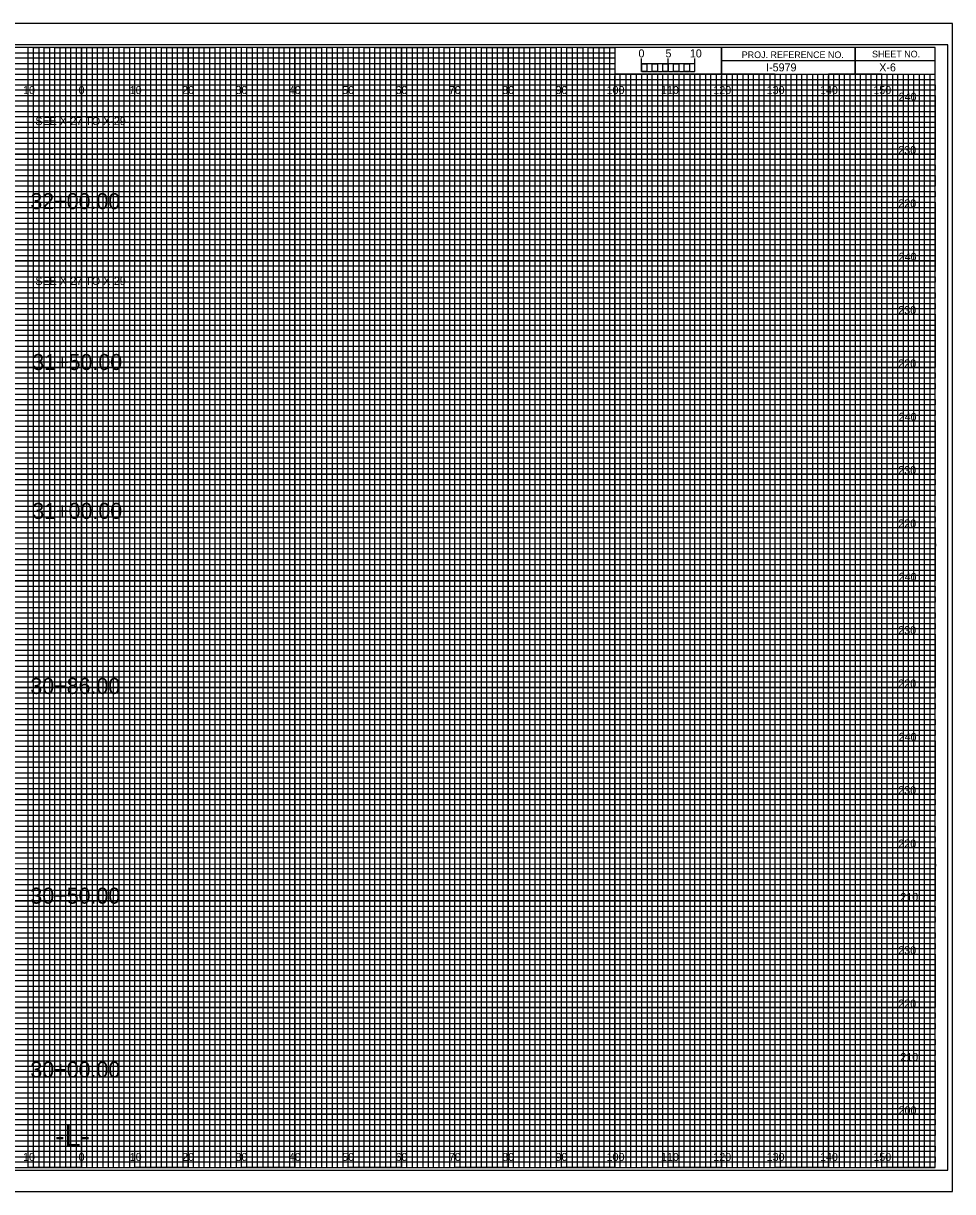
# Model space of a CAD drawing. Extents: x -13 to 359, y -5 to 2854.
# Drawn here: x 149.1 to 323.3, y 1095.5 to 1314.5 of the extents above; entities that cross this region are included whole.
import ezdxf

# ---------------------------------------------------------------- set-up
doc = ezdxf.new("R2010")
doc.units = 0
for name, color, linetype in [('Exist CMT Pavement', 7, 'Continuous'), ('Exist Cross Section Cell', 7, 'Continuous'), ('Exist XS Ground Line', 7, 'Continuous'), ('Prop CMT Conc Surface', 7, 'Continuous'), ('Prop CMT Concrete Structures', 7, 'Continuous'), ('Prop CMT DNC', 7, 'Continuous'), ('Prop CMT Pvmt Course 1', 7, 'Continuous'), ('Prop CMT Pvmt Course 1 CG', 7, 'Continuous'), ('Prop CMT Pvmt Course 1 Wedge', 7, 'Continuous'), ('Prop CMT Pvmt Course 2', 7, 'Continuous'), ('Prop CMT Pvmt Course 2 Wedge', 7, 'Continuous'), ('Prop CMT Pvmt Course 3', 7, 'Continuous'), ('Prop CMT Pvmt Course 3 Wedge', 7, 'Continuous'), ('Prop CMT Pvmt Wedge Surface 3', 7, 'Continuous'), ('Prop CMT Shear Line', 7, 'Continuous'), ('Prop CMT Slope Grass', 7, 'Continuous'), ('Prop CMT Subgrade Earthwork', 7, 'Continuous'), ('Scratch_Level_0', 7, 'Continuous')]:
    doc.layers.add(name, color=color, linetype=linetype)

msp = doc.modelspace()

# ---------------------------------------------------------------- linework, layer by layer
at = {"layer": 'Exist XS Ground Line'}
for p, q in [((150, 1310), (140, 1310)), ((150, 1100), (150, 1310)), ((170, 1310), (160, 1310)), ((160, 1310), (160, 1100)), ((170, 1100), (170, 1310)), ((190, 1310), (180, 1310)), ((180, 1310), (180, 1100)), ((190, 1100), (190, 1310)), ((210, 1310), (200, 1310)), ((200, 1310), (200, 1100)), ((210, 1100), (210, 1310)), ((230, 1310), (220, 1310)), ((220, 1310), (220, 1100)), ((230, 1100), (230, 1310)), ((250, 1310), (240, 1310)), ((240, 1310), (240, 1100)), ((250, 1100), (250, 1310)), ((260, 1310), (260, 1100)), ((270, 1100), (270, 1305)), ((290, 1305), (280, 1305)), ((280, 1305), (280, 1100)), ((290, 1100), (290, 1305)), ((310, 1305), (300, 1305)), ((300, 1305), (300, 1100)), ((310, 1100), (310, 1305)), ((160, 1100), (150, 1100)), ((180, 1100), (170, 1100)), ((200, 1100), (190, 1100)), ((220, 1100), (210, 1100)), ((240, 1100), (230, 1100)), ((260, 1100), (250, 1100)), ((280, 1100), (270, 1100)), ((300, 1100), (290, 1100)), ((320, 1100), (310, 1100)), ((320, 1100), (320, 1100))]:
    msp.add_line(p, q, dxfattribs=at)
for points in [[(0, 1300), (320, 1300), (320, 1290), (0, 1290)], [(0, 1280), (320, 1280), (320, 1270), (0, 1270)], [(0, 1260), (320, 1260), (320, 1250), (0, 1250)], [(0, 1240), (320, 1240), (320, 1230), (0, 1230)], [(0, 1220), (320, 1220), (320, 1210), (0, 1210)], [(0, 1200), (320, 1200), (320, 1190), (0, 1190)], [(0, 1180), (320, 1180), (320, 1170), (0, 1170)], [(0, 1160), (320, 1160), (320, 1150), (0, 1150)], [(0, 1140), (320, 1140), (320, 1130), (0, 1130)], [(0, 1120), (320, 1120), (320, 1110), (0, 1110)]]:
    msp.add_lwpolyline(points, dxfattribs=at)
at = {"layer": 'Prop CMT Conc Surface'}
for p, q in [((265, 1305.49), (265, 1307.9)), ((265, 1306.9), (265, 1307.9)), ((270, 1305.49), (270, 1307.9)), ((275, 1305.49), (275, 1307.9)), ((275, 1306.9), (275, 1307.9))]:
    msp.add_line(p, q, dxfattribs=at)
for points in [[(275, 1306.9), (265, 1306.9), (265, 1305.49), (275, 1305.49)], [(265, 1306.9), (266, 1306.9), (266, 1305.49), (265, 1305.49)], [(267, 1306.9), (268, 1306.9), (268, 1305.49), (267, 1305.49)], [(269, 1306.9), (270, 1306.9), (270, 1305.49), (269, 1305.49)], [(271, 1306.9), (272, 1306.9), (272, 1305.49), (271, 1305.49)], [(273, 1306.9), (274, 1306.9), (274, 1305.49), (273, 1305.49)]]:
    msp.add_lwpolyline(points, close=True, dxfattribs=at)
at = {"layer": 'Prop CMT Concrete Structures'}
for p, q in [((305, 1310), (305, 1305)), ((305, 1305), (305, 1310)), ((280, 1307.5), (280, 1305)), ((320, 1307.49), (280, 1307.49)), ((280, 1305), (320, 1305))]:
    msp.add_line(p, q, dxfattribs=at)
for points in [[(320, 1310), (0, 1310), (0, 1100), (320, 1100)], [(280, 1310), (260, 1310), (260, 1305.03), (280, 1305.03)], [(320, 1310), (280, 1310), (280, 1305), (320, 1305)]]:
    msp.add_lwpolyline(points, close=True, dxfattribs=at)
at = {"layer": 'Prop CMT DNC'}
for p, q in [((323.3, 1314.5), (-13.4, 1314.5)), ((-13.4, 1095.5), (323.3, 1095.5))]:
    msp.add_line(p, q, dxfattribs=at)
at = {"layer": 'Prop CMT Pvmt Course 1'}
for p, q in [((0, 1309), (260, 1309)), ((260, 1307.98), (0, 1307.98)), ((260, 1309), (260, 1307.98)), ((0, 1307), (260, 1307)), ((260, 1305.89), (0, 1305.89)), ((260, 1307), (260, 1305.89)), ((0, 1304), (320, 1304))]:
    msp.add_line(p, q, dxfattribs=at)
for points in [[(0, 1303), (270, 1303), (320, 1303), (320, 1302), (0, 1302)], [(0, 1301), (320, 1301), (320, 1299), (0, 1299)], [(0, 1298), (320, 1298), (320, 1297), (0, 1296.98)], [(0, 1296), (320, 1296), (320, 1294), (0, 1294)], [(0, 1293), (320, 1293), (320, 1292), (0, 1292)], [(0, 1291), (320, 1291), (320, 1289), (0, 1289)], [(0, 1288), (320, 1288), (320, 1287), (0, 1287)], [(0, 1286), (320, 1286), (320, 1284), (0, 1284)], [(0, 1283), (320, 1283), (320, 1282), (0, 1282)], [(0, 1281), (320, 1281), (320, 1279), (0, 1279)], [(0, 1278), (320, 1278), (320, 1277), (0, 1277)], [(0, 1276), (320, 1276), (320, 1273.95), (320, 1273), (320, 1272), (0, 1272)], [(0, 1274), (320, 1274), (320, 1273), (0, 1273)], [(0, 1271), (320, 1271), (320, 1269), (0, 1269.03)], [(0, 1269.03), (320, 1269), (320, 1268), (0, 1268)], [(0, 1267), (320, 1267), (320, 1266), (0, 1266)], [(0, 1264), (320, 1264), (320, 1263), (0, 1263)], [(0, 1262), (320, 1262), (320, 1261), (0, 1261)], [(-0.07, 1258.89), (320, 1258.89), (320, 1257.88), (-0.07, 1257.88)], [(0, 1257), (320, 1257), (320, 1256), (0, 1256)], [(0, 1254), (320, 1254), (320, 1253), (0, 1253)], [(0, 1252), (320, 1252), (320, 1251), (0, 1251)], [(0, 1249), (320, 1249), (320, 1248), (0, 1248)], [(0, 1247), (320, 1247), (320, 1246), (0, 1246)], [(0, 1244), (320, 1244), (320, 1243), (0, 1243)], [(0, 1242), (320, 1242), (320, 1241), (0, 1241)], [(0, 1239), (320, 1239), (319.99, 1237.98), (0, 1238)], [(0, 1237), (320, 1237), (320, 1236), (0, 1236)], [(0, 1234), (320, 1234), (320, 1233), (0, 1233)], [(0, 1232), (320, 1232), (320, 1231), (0, 1231)], [(0, 1229), (320, 1229), (320, 1228), (0, 1228)], [(0, 1227), (320, 1227), (320, 1226), (0, 1226)], [(0, 1224), (320, 1224), (320, 1223), (0, 1223)], [(0, 1222), (320, 1222), (320, 1221), (0, 1221)], [(0, 1219), (320, 1219), (320, 1218), (0, 1218)], [(0, 1216.99), (320.07, 1216.91), (320, 1216), (0, 1216)], [(0, 1214), (320, 1214), (320, 1213), (0, 1213)], [(0, 1212), (320, 1212), (320, 1211), (0, 1211)], [(0, 1209), (320, 1209), (320, 1208), (0, 1208)], [(0, 1207), (320, 1207), (320, 1206), (0, 1206)], [(0, 1204), (320, 1204), (320, 1203), (0, 1203)], [(0, 1202), (320, 1202), (320, 1201), (0, 1201)], [(0, 1199), (320, 1199), (320, 1198), (0, 1198)], [(0, 1197), (320, 1197), (320, 1196), (0, 1196)], [(0, 1194), (320, 1194), (320, 1193), (0, 1193)], [(0, 1192), (320, 1192), (320, 1191), (0, 1191)], [(0, 1189), (320, 1189), (320, 1188), (0, 1188)], [(0, 1187), (320, 1187), (320, 1186), (0, 1186)], [(0, 1184), (320, 1184), (320, 1183), (0, 1183)], [(0, 1182), (320, 1182), (320, 1181), (0, 1181)], [(0, 1179), (320, 1179), (319.99, 1177.98), (0, 1178)], [(0, 1177), (320, 1177), (320, 1176), (0, 1176)], [(0, 1174), (320, 1174), (320, 1173), (0, 1173)], [(0, 1172), (320, 1172), (320, 1171), (0, 1171)], [(0, 1169), (320, 1169), (320, 1168), (0, 1168)], [(0, 1167), (320, 1167), (320, 1166), (0, 1166)], [(0, 1164), (320, 1164), (320, 1163), (0, 1163)], [(0, 1162), (320, 1162), (320, 1161), (0, 1161)], [(0, 1159), (320, 1159), (320, 1158), (0, 1158)], [(0, 1156.99), (320.07, 1156.91), (320, 1156), (0, 1156)], [(0, 1154), (320, 1154), (320, 1153), (0, 1153)], [(0, 1152), (320, 1152), (320, 1151), (0, 1151)], [(0, 1149), (320, 1149), (320, 1148), (0, 1148)], [(0, 1147), (320, 1147), (320, 1146), (0, 1146)], [(0, 1144), (320, 1144), (320, 1143), (0, 1143)], [(0, 1142), (320, 1142), (320, 1141), (0, 1141)], [(0, 1139), (320, 1139), (320, 1138), (0, 1138)], [(0, 1137), (320, 1137), (320, 1136), (0, 1136)], [(0, 1134), (320, 1134), (320, 1133), (0, 1133)], [(0, 1132), (320, 1132), (320, 1131), (0, 1131)], [(0, 1129), (320, 1129), (320, 1128), (0, 1128)], [(0, 1127), (320, 1127), (320, 1126), (0, 1126)], [(0, 1124), (320, 1124), (320, 1123), (0, 1123)], [(0, 1122), (320, 1122), (320, 1121), (0, 1121)], [(0, 1119), (320, 1119), (320, 1118), (0, 1118)], [(0, 1117), (320, 1117), (320, 1116), (0, 1116)], [(0, 1114), (320, 1114), (320, 1113), (0, 1113)], [(0, 1112), (320, 1112), (320, 1111), (0, 1111)], [(0, 1109), (320, 1109), (320, 1108), (0, 1108)], [(0, 1107), (320, 1107), (320, 1106), (0, 1106)], [(0, 1104), (320, 1104), (320, 1103), (0, 1103)], [(0, 1102), (320, 1102), (320, 1101), (0, 1101)]]:
    msp.add_lwpolyline(points, dxfattribs=at)
at = {"layer": 'Prop CMT Pvmt Course 1 CG'}
for p, q in [((267, 1305), (266.01, 1305)), ((266.01, 1305), (266.01, 1100)), ((267, 1100), (267, 1305)), ((269, 1305), (268, 1305)), ((268, 1305), (268, 1100)), ((269, 1100), (269, 1305)), ((266.01, 1100), (265, 1100)), ((268, 1100), (267, 1100))]:
    msp.add_line(p, q, dxfattribs=at)
for points in [[(150, 1100), (151, 1100), (151, 1310), (152, 1310), (152, 1100)], [(152, 1100), (153, 1100), (153, 1310), (154, 1310), (154, 1100)], [(155, 1100), (156, 1100), (156, 1310), (157, 1310), (157, 1100)], [(157, 1100), (158, 1100), (158, 1310), (159, 1310), (159, 1100)], [(160, 1100), (161, 1100), (161, 1310), (162, 1310), (162, 1100)], [(162, 1100), (163, 1100), (163, 1310), (164, 1310), (164, 1100)], [(165, 1100), (166, 1100), (166, 1310), (167, 1310), (167, 1100)], [(167, 1100), (168, 1100), (168, 1310), (169, 1310), (169, 1100)], [(170, 1100), (171, 1100), (171, 1310), (172, 1310), (172, 1100)], [(172, 1100), (173, 1100), (173, 1310), (174, 1310), (174, 1100)], [(175, 1100), (176, 1100), (176, 1310), (177, 1310), (177, 1100)], [(177, 1100), (178, 1100), (178, 1310), (179, 1310), (179, 1100)], [(180, 1100), (181, 1100), (181, 1310), (182, 1310), (182, 1100)], [(182, 1100), (183, 1100), (183, 1310), (184, 1310), (184, 1100)], [(185, 1100), (186, 1100), (186, 1310), (187, 1310), (187, 1100)], [(187, 1100), (188, 1100), (188, 1310), (189, 1310), (189, 1100)], [(190, 1100), (191, 1100), (191, 1310), (192, 1310), (192, 1100)], [(192, 1100), (193, 1100), (193, 1310), (194, 1310), (194, 1100)], [(195, 1100), (196, 1100), (196, 1310), (197, 1310), (197, 1100)], [(197, 1100), (198, 1100), (198, 1310), (199, 1310), (199, 1100)], [(200, 1100), (201, 1100), (201, 1310), (202, 1310), (202, 1100)], [(202, 1100), (203, 1100), (203, 1310), (204, 1310), (204, 1100)], [(205, 1100), (206, 1100), (206, 1310), (207, 1310), (207, 1100)], [(207, 1100), (208, 1100), (208, 1310), (209, 1310), (209, 1100)], [(210, 1100), (211, 1100), (211, 1310), (212, 1310), (212, 1100)], [(212, 1100), (213, 1100), (213, 1310), (214, 1310), (214, 1100)], [(215, 1100), (216, 1100), (216, 1310), (217, 1310), (217, 1100)], [(217, 1100), (218, 1100), (218, 1310), (219, 1310), (219, 1100)], [(220, 1100), (221, 1100), (221, 1310), (222, 1310), (222, 1100)], [(222, 1100), (223, 1100), (223, 1310), (224, 1310), (224, 1100)], [(225, 1100), (226, 1100), (226, 1310), (227, 1310), (227, 1100)], [(227, 1100), (228, 1100), (228, 1310), (229, 1310), (229, 1100)], [(230, 1100), (231, 1100), (231, 1310), (232, 1310), (232, 1100)], [(232, 1100), (233, 1100), (233, 1310), (234, 1310), (234, 1100)], [(235, 1100), (236, 1100), (236, 1310), (237, 1310), (237, 1100)], [(237, 1100), (238, 1100), (238, 1310), (239, 1310), (239, 1100)], [(240, 1100), (241, 1100), (241, 1310), (242, 1310), (242, 1100)], [(242, 1100), (243, 1100), (243, 1310), (244, 1310), (244, 1100)], [(245, 1100), (246, 1100), (246, 1310), (247, 1310), (247, 1100)], [(247, 1100), (248, 1100), (248, 1310), (249, 1310), (249, 1100)], [(250, 1100), (251, 1100), (251, 1310), (252, 1310), (252, 1100)], [(252, 1100), (253, 1100), (253, 1310), (254, 1310), (254, 1100)], [(255, 1100), (256, 1100), (256, 1310), (257, 1310), (257, 1100)], [(257, 1100), (258, 1100), (258, 1310), (259, 1310), (259, 1100)], [(260, 1100), (261, 1100), (261, 1305), (262.02, 1305), (262.02, 1100)], [(262, 1100), (263, 1100), (263, 1305), (263.99, 1305), (263.99, 1100)], [(270, 1100), (270.98, 1100), (270.98, 1305), (272, 1305), (272, 1100)], [(272, 1100), (273, 1100), (273, 1305), (274.05, 1305), (274.05, 1100)], [(275, 1100), (276, 1100), (276, 1305), (277, 1305), (277, 1100)], [(277, 1100), (278, 1100), (278, 1305), (279, 1305), (279, 1100)], [(280, 1100), (281, 1100), (281, 1305), (282, 1305), (282, 1100)], [(282, 1100), (283, 1100), (283, 1305), (284, 1305), (284, 1100)], [(285, 1100), (286, 1100), (286, 1305), (287, 1305), (287, 1100)], [(287, 1100), (288, 1100), (288, 1305), (289, 1305), (289, 1100)], [(290, 1100), (291, 1100), (291, 1305), (292, 1305), (292, 1100)], [(292, 1100), (293, 1100), (293, 1305), (294, 1305), (294, 1100)], [(295, 1100), (296, 1100), (296, 1305), (297, 1305), (297, 1100)], [(297, 1100), (298, 1100), (298, 1305), (299, 1305), (299, 1100)], [(300, 1100), (301, 1100), (301, 1305), (302, 1305), (302, 1100)], [(302, 1100), (303, 1100), (303, 1305), (304, 1305), (304, 1100)], [(305, 1100), (306, 1100), (306, 1305), (307, 1305), (307, 1100)], [(307, 1100), (308, 1100), (308, 1305), (309, 1305), (309, 1100)], [(310, 1100), (311, 1100), (311, 1305), (312, 1305), (312, 1100)], [(312, 1100), (313, 1100), (313, 1305), (314, 1305), (314, 1100)], [(315, 1100), (316, 1100), (316, 1305), (317, 1305), (317, 1100)], [(317, 1100), (318, 1100), (318, 1305), (319, 1305), (319, 1100)]]:
    msp.add_lwpolyline(points, dxfattribs=at)
at = {"layer": 'Prop CMT Shear Line'}
for p, q in [((150, 1100), (150, 1310)), ((160, 1100), (160, 1310)), ((170, 1100), (170, 1310)), ((180, 1100), (180, 1310)), ((190, 1100), (190, 1310)), ((200, 1100), (200, 1310)), ((210, 1100), (210, 1310)), ((220, 1100), (220, 1310)), ((230, 1100), (230, 1310)), ((240, 1100), (240, 1310)), ((250, 1100), (250, 1310)), ((260, 1100), (260, 1304.69)), ((270, 1100), (270, 1304.69)), ((280, 1100), (280, 1304.69)), ((290, 1100), (290, 1304.69)), ((300, 1100), (300, 1304.69)), ((310, 1100), (310, 1304.69)), ((0, 1300), (320, 1300)), ((0, 1290), (320, 1290)), ((0, 1280), (320, 1280)), ((0, 1270), (320, 1270)), ((0, 1260), (320, 1260)), ((0, 1250), (320, 1250)), ((0, 1240), (320, 1240)), ((0, 1230), (320, 1230)), ((0, 1220), (320, 1220)), ((0, 1210), (320, 1210)), ((0, 1200), (320, 1200)), ((0, 1190), (320, 1190)), ((0, 1180), (320, 1180)), ((0, 1170), (320, 1170)), ((0, 1160), (320, 1160)), ((0, 1150), (320, 1150)), ((0, 1140), (320, 1140)), ((0, 1130), (320, 1130)), ((0, 1120), (320, 1120)), ((0, 1110), (320, 1110))]:
    msp.add_line(p, q, dxfattribs=at)
at = {"layer": 'Prop CMT Slope Grass'}
msp.add_lwpolyline([(-10.8, 1099.5), (322.4, 1099.5), (322.4, 1310.5), (-10.8, 1310.5)], close=True, dxfattribs=at)
at = {"layer": 'Prop CMT Subgrade Earthwork'}
msp.add_lwpolyline([(-13.4, 1095.5), (323.3, 1095.5), (323.3, 1314.5), (-13.4, 1314.5)], close=True, dxfattribs=at)
at = {"layer": 'Scratch_Level_0'}
for points in [[(145, 1100), (155, 1100), (155, 1310), (165, 1310), (165, 1100), (175, 1100), (175, 1310), (185, 1310), (185, 1100), (195, 1100), (195, 1310), (205, 1310), (205, 1100), (215, 1100), (215, 1310), (225, 1310), (225, 1100), (235, 1100), (235, 1310), (245, 1310), (245, 1100), (255, 1100), (255, 1310), (259.93, 1310), (260, 1310), (260, 1305), (264.99, 1305), (264.99, 1100), (275, 1100), (275, 1305), (285, 1305), (285, 1100), (295, 1100), (295, 1305), (305, 1305), (305, 1100), (315, 1100), (315, 1305)], [(0, 1305), (275, 1305)], [(0, 1285), (320, 1285), (320, 1295), (0, 1295)], [(0, 1265), (320, 1265), (320, 1275), (0, 1275)], [(0, 1245), (320, 1245), (320, 1255), (0, 1255)], [(0, 1225), (320, 1225), (320, 1235), (0, 1235)], [(0, 1205), (320, 1205), (320, 1215), (0, 1215)], [(0, 1185), (320, 1185), (320, 1195), (0, 1195)], [(0, 1165), (320, 1165), (320, 1175), (0, 1175)], [(0, 1145), (320, 1145), (320, 1155), (0, 1155)], [(0, 1125), (320, 1125), (320, 1135), (0, 1135)], [(0, 1105), (320, 1105), (320, 1115), (0, 1115)]]:
    msp.add_lwpolyline(points, dxfattribs=at)

# ---------------------------------------------------------------- texts
at = {"layer": 'Exist CMT Pavement'}
for s, p in [('5', (269.47, 1308.12)), ('10', (274.04, 1308.12))]:
    msp.add_text(s, height=1.5, dxfattribs=at).set_placement(p)
at = {"layer": 'Exist Cross Section Cell'}
for s, p in [('10', (149.04, 1301.25)), ('0', (159.45, 1301.25)), ('0', (159.45, 1301.25)), ('10', (169.04, 1301.25)), ('20', (178.86, 1301.25)), ('30', (188.86, 1301.25)), ('40', (198.86, 1301.25)), ('50', (208.86, 1301.25)), ('60', (218.86, 1301.25)), ('70', (228.86, 1301.25)), ('80', (238.86, 1301.25)), ('90', (248.86, 1301.25)), ('100', (258.44, 1301.25)), ('110', (268.62, 1301.25)), ('120', (278.44, 1301.25)), ('130', (288.44, 1301.25)), ('140', (298.44, 1301.25)), ('150', (308.44, 1301.25)), ('10', (149.04, 1101.25)), ('0', (159.45, 1101.25)), ('0', (159.45, 1101.25)), ('10', (169.04, 1101.25)), ('20', (178.86, 1101.25)), ('30', (188.86, 1101.25)), ('40', (198.86, 1101.25)), ('50', (208.86, 1101.25)), ('60', (218.86, 1101.25)), ('70', (228.86, 1101.25)), ('80', (238.86, 1101.25)), ('90', (248.86, 1101.25)), ('100', (258.44, 1101.25)), ('110', (268.62, 1101.25)), ('120', (278.44, 1101.25)), ('130', (288.44, 1101.25)), ('140', (298.44, 1101.25)), ('150', (308.44, 1101.25))]:
    msp.add_text(s, height=1.5, dxfattribs=at).set_placement(p)
at = {"layer": 'Prop CMT Conc Surface'}
msp.add_text('0', height=1.5, dxfattribs=at).set_placement((264.41, 1308.12))
at = {"layer": 'Prop CMT Concrete Structures'}
for s, p in [('PROJ. REFERENCE NO.', (283.77, 1307.99)), ('SHEET NO.', (308.19, 1308.12))]:
    msp.add_text(s, height=1.25, dxfattribs=at).set_placement(p)
at = {"layer": 'Prop CMT Pvmt Course 1 Wedge'}
msp.add_text('X-6', height=1.5, dxfattribs=at).set_placement((309.54, 1305.5))
at = {"layer": 'Prop CMT Pvmt Course 2'}
for s, p in [('240', (313.19, 1300)), ('230', (313.11, 1290)), ('220', (313.12, 1280)), ('240', (313.19, 1270)), ('230', (313.11, 1260)), ('220', (313.12, 1250)), ('240', (313.19, 1240)), ('230', (313.11, 1230)), ('220', (313.12, 1220)), ('240', (313.19, 1210)), ('230', (313.11, 1200)), ('220', (313.12, 1190)), ('240', (313.19, 1180)), ('230', (313.11, 1170)), ('220', (313.12, 1160)), ('210', (313.5, 1150)), ('230', (313.11, 1140)), ('220', (313.12, 1130)), ('210', (313.5, 1120)), ('200', (313.17, 1110))]:
    msp.add_text(s, height=1.5, dxfattribs=at).set_placement(p)
at = {"layer": 'Prop CMT Pvmt Course 2 Wedge'}
msp.add_text('I-5979', height=1.5, dxfattribs=at).set_placement((288.34, 1305.5))
at = {"layer": 'Prop CMT Pvmt Course 3'}
for s, p in [('32+00.00', (150.41, 1279.68)), ('31+50.00', (150.77, 1249.52)), ('31+00.00', (150.77, 1221.62)), ('30+86.00', (150.41, 1188.79)), ('30+50.00', (150.41, 1149.48)), ('30+00.00', (150.41, 1116.88))]:
    msp.add_text(s, height=3, dxfattribs=at).set_placement(p)
at = {"layer": 'Prop CMT Pvmt Course 3 Wedge'}
msp.add_text('-L-', height=4, dxfattribs=at).set_placement((155.06, 1104))
at = {"layer": 'Prop CMT Pvmt Wedge Surface 3'}
for p in [(151.34, 1295.44), (151.34, 1265.46)]:
    msp.add_text('SEE X-27 TO X-29', height=1.5, rotation=360, dxfattribs=at).set_placement(p)

doc.saveas('drawing.dxf')
